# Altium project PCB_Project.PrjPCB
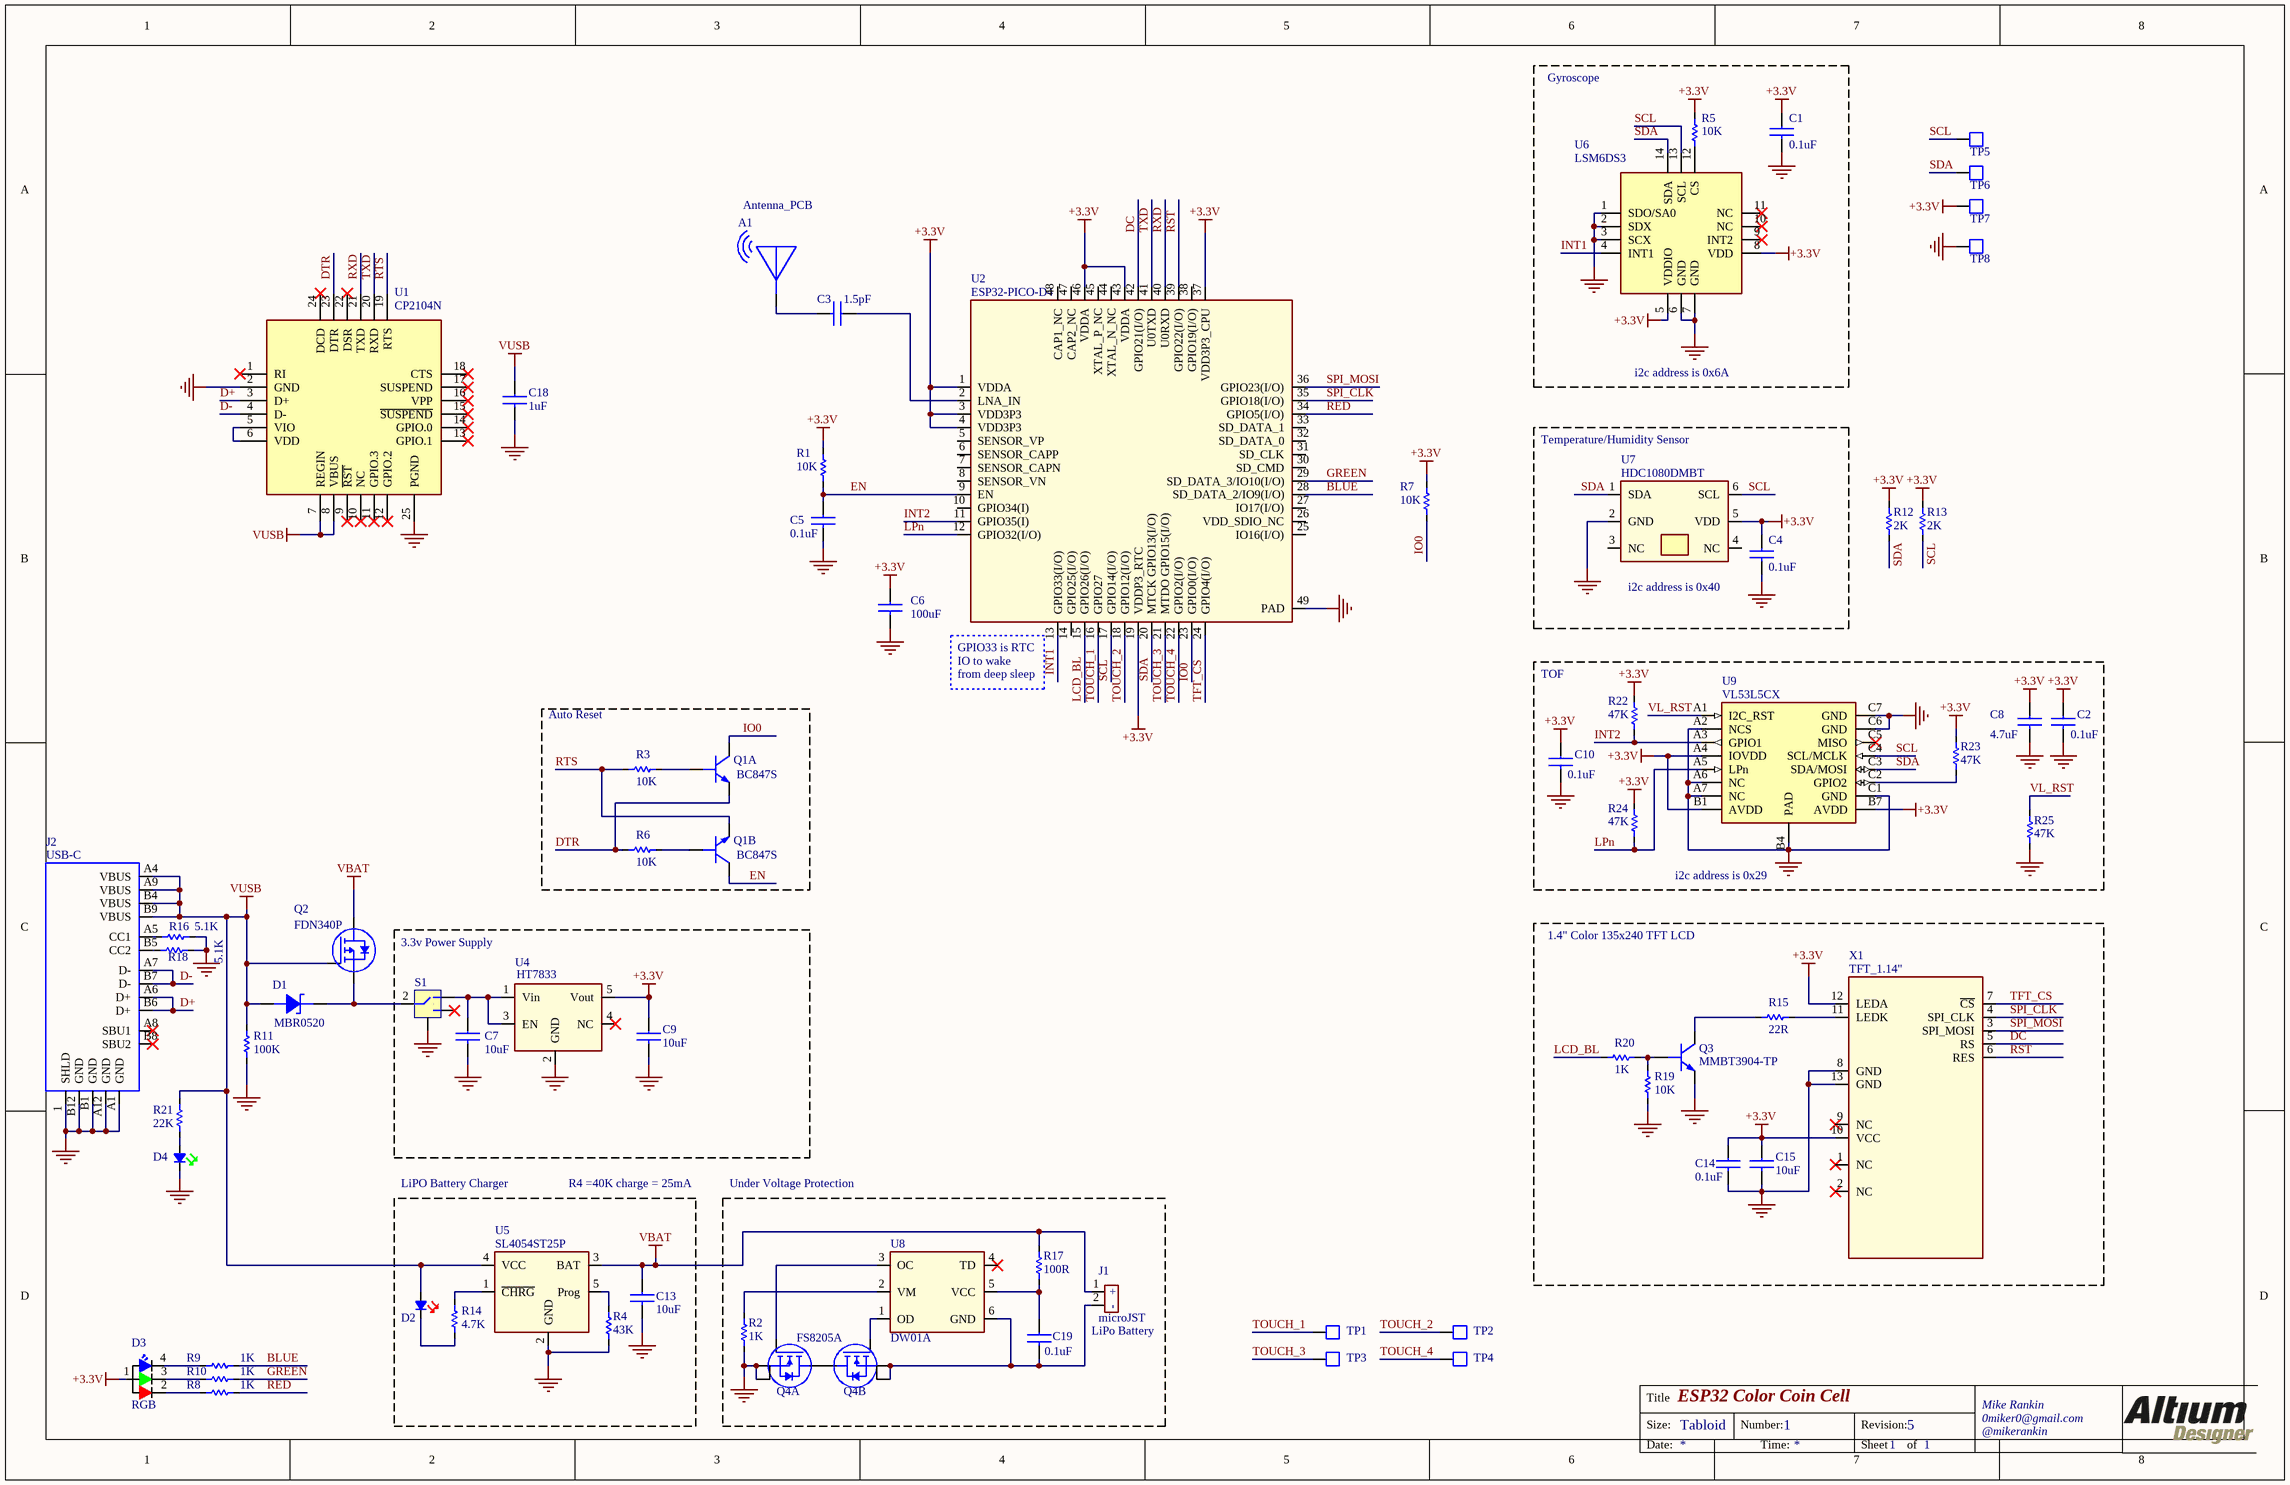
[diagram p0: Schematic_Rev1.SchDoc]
1 sheet, 69 parts. Net scope: global (net labels, ports and power ports of the same name join across sheets).
Board file: PCB_Sensor_Rev1.PcbDoc

## Sheet Schematic_Rev1.SchDoc: ESP32 Color Coin Cell
size Tabloid; DrawnBy: x; Engineer: x; Address1: Mike Rankin; Address2: 0miker0@gmail.com; Address3: @mikerankin; DocumentNumber: 1; Revision: 5; SheetNumber: 1; SheetTotal: 1

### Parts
A1  Antenna_PCB  [ANTENNA PCB]
C1  0.1uF  [CAPC1005X56N]
C2  0.1uF  [CAPC1005X56N]
C3  1.5pF  [CAPC1005X56N]
C4  0.1uF  [CAPC1005X56N]
C5  0.1uF  [CAPC1005X56N]
C6  100uF  [CAPC3216X160L]
C7  10uF  [CAPC2012X140N]
C8  4.7uF  [CAPC2012X140N]
C9  10uF  [CAPC2012X140N]
C10  0.1uF  [CAPC1005X56N]
C13  10uF  [CAPC2012X140N]
C14  0.1uF  [CAPC1005X56N]
C15  10uF  [CAPC2012X140N]
C18  1uF  [CAPC1005X56N]
C19  0.1uF  [CAPC1005X56N]
D1  MBR0520  [SOD123]
D2  Red Led  [LED1005X40N-Red]  (value not drawn)
D3  RGB  [FC-B1010RGBT-HG]
D4  Green Led  [LED1005X40N-Green]  (value not drawn)
J1  CON2  [JST_Micro_2PIN]  (value not drawn)  (no BOM)
J2  USB-C  [TYPE-C-31-M-12]
Q1  BC847S  [SOT65P210X110-6N]  (parts A,B of 2)
Q2  FDN340P  [SOT95P240X110-3N]
Q3  MMBT3904-TP  [SOT95P240X110-3N]
Q4  FS8205A  [TSOP65P490X110-8N WIDE]  (value not drawn)  (parts A,B of 2)
R1  10K  [RESC1005X40L]
R2  1K  [RESC1005X40L]
R3  10K  [RESC1005X40L]
R4  43K  [RESC1005X40L]
R5  10K  [RESC1005X40L]
R6  10K  [RESC1005X40L]
R7  10K  [RESC1005X40L]
R8  1K  [RESC1005X40L]
R9  1K  [RESC1005X40L]
R10  1K  [RESC1005X40L]
R11  100K  [RESC1005X40L]
R12  2K  [RESC1005X40L]
R13  2K  [RESC1005X40L]
R14  4.7K  [RESC1005X40L]
R15  22R  [RESC1005X40L]
R16  5.1K  [RESC1005X40L]
R17  100R  [RESC1005X40L]
R18  5.1K  [RESC1005X40L]
R19  10K  [RESC1005X40L]
R20  1K  [RESC1005X40L]
R21  22K  [RESC1005X40L]
R22  47K  [RESC1005X40L (0402 FOOTPRINT)]
R23  47K  [RESC1005X40L (0402 FOOTPRINT)]
R24  47K  [RESC1005X40L (0402 FOOTPRINT)]
R25  47K  [RESC1005X40L (0402 FOOTPRINT)]
S1  SWITCH SLIDE  [K3-1296S-E1]  (value not drawn)
TP1  Test Point, 1mm Top Layer  [TP100TL]  (value not drawn)  (no BOM)
TP2  Test Point, 1mm Top Layer  [TP100TL]  (value not drawn)  (no BOM)
TP3  Test Point, 1mm Top Layer  [TP100TL]  (value not drawn)  (no BOM)
TP4  Test Point, 1mm Top Layer  [TP100TL]  (value not drawn)  (no BOM)
TP5  Test Point, 1mm Top Layer  [TP100TL]  (value not drawn)  (no BOM)
TP6  Test Point, 1mm Top Layer  [TP100TL]  (value not drawn)  (no BOM)
TP7  Test Point, 1mm Top Layer  [TP100TL]  (value not drawn)  (no BOM)
TP8  Test Point, 1mm Top Layer  [TP100TL]  (value not drawn)  (no BOM)
U1  CP2104N  [24-QFN]
U2  ESP32-PICO-D4  [QFN48_NEWEST]
U4  HT7833  [SOT95P280X144-5N]
U5  SL4054ST25P  [SOT95P280X144-5N]
U6  LSM6DS3  [LSM6DS3]
U7  HDC1080DMBT  [HDC1080]
U8  DW01A  [SOT95P280X130-6N]
U9  value VL53L5CX  [VL53L5CPV0GC/1]  (hidden comment: TOF Sensor)
X1  TFT_1.14"  [TFT_GLASS 1.14 INCH]

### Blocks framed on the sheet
Auto Reset: Q1 R3 R6
3.3v Power Supply: C7 C9 S1 U4
1.4" Color 135x240 TFT LCD: C14 C15 Q3 R15 R19 R20 X1

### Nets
+3.3V: C1.1 C2.1 C4.1 C6.1 C8.1 C9.1 C10.1 C14.1 C15.1 D3.1 R1.1 R5.1 R7.1 R12.2 R13.2 R22.2 R23.2 R24.2 TP7.1 U2.1(VDDA) U2.3(VDD3P3) U2.4(VDD3P3) U2.19(VDDP3_RTC) U2.37(VDD3P3_CPU) U2.43(VDDA) U2.46(VDDA) U4.5(Vout) U6.5(VDDIO) U6.8(VDD) U7.5(VDD) U9.A4(IOVDD) U9.B1(AVDD) U9.B7(AVDD) X1.10(VCC) X1.12(LEDA)
GND: C1.2 C2.2 C4.2 C5.2 C6.2 C7.2 C8.2 C9.2 C10.2 C13.2 C14.2 C15.2 C18.2 D4.1 J2.1(SHLD) J2.A1(GND) J2.A12(GND) J2.B1(GND) J2.B12(GND) Q3.2(E) Q4.2(S) Q4.3(S) R2.1 R4.2 R11.2 R16.2 R18.2 R19.2 R25.1 S1.4 TP8.1 U1.2(GND) U1.25(PGND) U2.49(PAD) U4.2(GND) U5.2(GND) U6.1(SDO/SA0) U6.2(SDX) U6.3(SCX) U6.6(GND) U6.7(GND) U7.2(GND) U9.A2(NCS) U9.A6(NC) U9.A7(NC) U9.B4(PAD) U9.C1(GND) U9.C6(GND) U9.C7(GND) X1.8(GND) X1.13(GND)
VBAT: C13.1 J1.1 Q2.3(D) R17.2 U5.3(BAT)
VUSB: C18.1 D1.2(Annode) D2.2 J2.A4(VBUS) J2.A9(VBUS) J2.B4(VBUS) J2.B9(VBUS) Q2.1(G) R11.1 R21.2 U1.7(REGIN) U1.8(VBUS) U5.4(VCC)
BLUE: R9.2 U2.28(SD_DATA_2/IO9(I/O))
D+: J2.A6(D+) J2.B6(D+) U1.3(D+)
D-: J2.A7(D-) J2.B7(D-) U1.4(D-)
DC: U2.42(GPIO21(I/O)) X1.5(RS)
DTR: Q1.1(E1) R6.2 U1.23(DTR)
EN: C5.1 Q1.3(C2) R1.2 U2.9(EN)
GREEN: R10.2 U2.29(SD_DATA_3/IO10(I/O))
INT1: U2.13(GPIO33(I/O)) U6.4(INT1)
INT2: R22.1 U2.11(GPIO35(I)) U9.A3(GPIO1)
IO0: Q1.6(C1) R7.2 U2.23(GPIO0(I/O))
LCD_BL: R20.1 U2.15(GPIO26(I/O))
LPn: R24.1 U2.12(GPIO32(I/O)) U9.A5(LPn)
RED: R8.2 U2.34(GPIO5(I/O))
RST: U2.39(GPIO22(I/O)) X1.6(RES)
RTS: Q1.4(E2) R3.2 U1.19(RTS)
RXD: U1.21(TXD) U2.40(U0RXD)
SCL: R13.1 TP5.1 U2.17(GPIO14(I/O)) U6.13(SCL) U7.6(SCL) U9.C4(SCL/MCLK)
SDA: R12.1 TP6.1 U2.20(MTCK_GPIO13(I/O)) U6.14(SDA) U7.1(SDA) U9.C3(SDA/MOSI)
SPI_CLK: U2.35(GPIO18(I/O)) X1.4(SPI_CLK)
SPI_MOSI: U2.36(GPIO23(I/O)) X1.3(SPI_MOSI)
TFT_CS: U2.24(GPIO4(I/O)) X1.7(~{CS})
TOUCH_1: TP1.1 U2.16(GPIO27)
TOUCH_2: TP2.1 U2.18(GPIO12(I/O))
TOUCH_3: TP3.1 U2.21(MTDO_GPIO15(I/O))
TOUCH_4: TP4.1 U2.22(GPIO2(I/O))
TXD: U1.20(RXD) U2.41(U0TXD)
VL_RST: R25.2 U9.A1(I2C_RST)
NetA1_1: A1.1 C3.2
NetC3_1: C3.1 U2.2(LNA_IN)
NetC7_1: C7.1 S1.1 U4.1(Vin) U4.3(EN)
NetC19_1: C19.1 R17.1 U8.5(VCC)
NetC19_2: C19.2 J1.2 Q4.6(S) Q4.7(S) U8.6(GND)
NetD1_1: D1.1(Cathode) Q2.2(S) S1.2
NetD2_1: D2.1 R14.1
NetD3_2: D3.2 R8.1
NetD3_3: D3.3 R10.1
NetD3_4: D3.4 R9.1
NetD4_2: D4.2 R21.1
NetJ2_A5: J2.A5(CC1) R16.1
NetJ2_B5: J2.B5(CC2) R18.1
NetQ1_2: Q1.2(B1) R3.1
NetQ1_5: Q1.5(B2) R6.1
NetQ3_1: Q3.1(B) R19.1 R20.2
NetQ3_3: Q3.3(C) R15.2
NetQ4_1: Q4.1(D) Q4.8(D)
NetQ4_4: Q4.4(G) U8.3(OC)
NetQ4_5: Q4.5(G) U8.1(OD)
NetR2_2: R2.2 U8.2(VM)
NetR4_1: R4.1 U5.5(Prog)
NetR5_2: R5.2 U6.12(CS)
NetR14_2: R14.2 U5.1(~{CHRG})
NetR15_1: R15.1 X1.11(LEDK)
NetR23_1: R23.1 U9.C2(GPIO2)
NetU1_5: U1.5(VIO) U1.6(VDD)

Not connected (* = marked no-connect by the designer): J2 A8(SBU1)* B8(SBU2)*; S1 3*; U1 1(RI)* 9(~{RST})* 10(NC)* 11(GPIO.3)* 12(GPIO.2)* 13(GPIO.1)* 14(GPIO.0)* 15(~{SUSPEND})* 16(VPP)* 17(SUSPEND)* 18(CTS)* 22(DSR)* 24(DCD)*; U2 5(SENSOR_VP) 6(SENSOR_CAPP) 7(SENSOR_CAPN) 8(SENSOR_VN) 10(GPIO34(I)) 14(GPIO25(I/O)) 25(IO16(I/O)) 26(VDD_SDIO_NC) 27(IO17(I/O)) 30(SD_CMD) 31(SD_CLK) 32(SD_DATA_0) 33(SD_DATA_1) 38(GPIO19(I/O)) 44(XTAL_N_NC) 45(XTAL_P_NC) 47(CAP2_NC) 48(CAP1_NC); U4 4(NC)*; U6 9(INT2)* 10(NC)* 11(NC)*; U7 3(NC) 4(NC); U8 4(TD)*; U9 C5(MISO)*; X1 1(NC)* 2(NC)* 9(NC)*

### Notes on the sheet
- Gyroscope
- i2c address is 0x6A
- (near U7) Temperature/Humidity Sensor
- i2c address is 0x40
- (near U2) GPIO33 is RTC
- (near U2) IO to wake
- (near U2) from deep sleep
- TOF
- i2c address is 0x29
- LiPO Battery Charger
- R4 =40K charge = 25mA
- Under Voltage Protection
- (near J1) LiPo Battery
- (near J1) microJST
- Labels drawn without touching a wire or pin: ~{}

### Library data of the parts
A1 = Antenna_PCB: Antenna PCB 2.4G; Value: PCB Antenna
C1 C2 C4 C5 C10 C14 C19 = CAP_0402: CAP 0.1uF 0402; PartNumber: C344190; Manufacturer: CCTC; Vendor: LCSC
C3 = CAP_0402: CAP 1.5pF 0402; Part_Number: C147344; Manufacturer: Dafron; Part_Footprint: 0402; Vendor: LCSC
C6 = CAP_1206: CAP 100uF 6.3V 1206; PartNumber: C87164; Manufacturer: Taiyo Yuden; Vendor: LCSC
C7 C9 C15 = CAP_0805: CAP 10uF 0805; Manufacturer: Samsung; PartNumber: C307520; Vendor: LCSC
C8 = CAP_0805: CAP 4.7uF 0805
C13 = CAP_0805: CAP 10uF 0805; PartNumber: C307520; Manufacturer: Samsung; Vendor: LCSC
C18 = CAP_0603: CAP 1uF 16V 0402; PartNumber: C83063; Manufacturer: Walsin; Vendor: LCSC
D1 = MBR0520-TP: DIODE SCHOTTKY 20V 500MA SOD123; Manufacturer: CJ; PartNumber: C475717; Vendor: LCSC
D2 = LED_0402_SMALL_Red: LED RED 0603; Part_Number: C364556; Part_Footprint: 0402; Vendor: LCSC
D3 = FC-B1010RGBT-HG: LED,RGB LED,SMD,RoHS; PartNumber: C158099; Manufacturer: Foshan; Vendor: LCSC; Value: RGB Led
D4 = LED_0402_SMALL_GREEN: LED Green 0402; Part_Number: C74338; Part_Footprint: 0402; Vendor: LCSC
J1 = JST_Micro_CONN_2PIN: JST MIcro CONN 2POS
J2 = USB-C: CONN RECPT USB-C; Manufacturer: KHE; Part_Number: C165948; Part_Footprint: SMT; Vendor: LCSC
Q1 = BC847S: TRANS 2NPN 44V 0.1A SC-70-6; Manufacturer: Changjiang; Vendor: LCSC
Q2 = FDN340P: MOSFET P-CH 20V 2A SOT-23; Manufacturer: On Semi; Part_Number: C75469; Vendor: LCSC
Q3 = MMBT3904-TP: TRANSISTOR NPN SOT23; Manufacturer: Micro Commercial; PartNumber: C668969; Vendor: LCSC
Q4 = FS8205A: MOSFET 2N-CH 20V 6A TSSOP-8L; Manufacturer: Fortune; PartNumber: C16052; Vendor: LCSC
R1 R3 R5-R7 R19 = RES_0402: RES 10K 0402; PartNumber: C258091; Manufacturer: Guangdong; Vendor: LCSC
R2 R8-R10 R20 = RES_0402: RES 1K 0402; PartNumber: C106235; Manufacturer: Yageo; Vendor: LCSC
R4 = RES_0603: RES 43K 0402; Manufacturer: Uniroyal; PartNumber: C8329; Vendor: LCSC
R11 = RES_0603: RES 100K 0402; Manufacturer: Uniroyal Elec; PartNumber: C25741; Vendor: LCSC
R12 R13 = RES_0402: RES 2K 0402; Manufacturer: LIZ Elec; PartNumber: C100291; Vendor: LCSC
R14 = RES_0603: RES 4.7K 0402; Manufacturer: LIZ Elec; PartNumber: C100139; Vendor: LCSC
R15 = RES_0402: RES 22R 0402; PartNumber: C25092; Manufacturer: Uniroyal; Vendor: LCSC
R16 R18 = RES_0603: RES 5.1K 0402; Vendor: LCSC
R17 = RES_0603: RES 100R 0402; Manufacturer: Yageo; PartNumber: C106232; Vendor: LCSC
R21 = RES_0603: RES 22K 0402; Manufacturer: LIZ Elec; PartNumber: C100310; Vendor: LCSC
R22-R25 = RES_0402: RES 47K 0402; Vendor: LCSC
S1 = K3-1296S-E1: SWITCH SLIDE SMD; Manufacturer: Korean Hroparts Elec; PartNumber: C128955; Vendor: LCSC
U1 = CP2104N: IC BRIDGE USB TO UART 24QFN; Manufacturer: Silicon Labs; PartNumber: C47742; Vendor: LCSC
U2 = ESP32-PICO-D4: RF Transceiver ICs QFN-48_7x7x05P RoHS; Manufacturer: Espressif; PartNumber: C193707; Vendor: LCSC
U4 = HT7833: IC LDO 3.3V 0.5A SOT23-5; Manufacturer: Holtek; PartNumber: C164106; Vendor: LCSC
U5 = SL4054ST25P: Charger IC Lithium-Ion/Polymer SOT23-5; Manufacturer: Techfuse; PartNumber: C258510; Vendor: LCSC
U6 = LSM6DS3 (obsolete): IMU ACCEL/GYRO I2C/SPI 14VFLGA; Manufacturer: ST MICRO; Part_Number: LSM6DS3TR; Vendor: LCSC
U7 = HDC1080DMBT: Humidity/Temperature Sensor; Manufacturer: Texas Instruments; PartNumber: C82227; Vendor: LCSC
U8 = DW01A: IC LITHIUM BATT PROTECT SOT-23-6L; Manufacturer: PUOLOP; PartNumber: C351410; Vendor: LCSC
U9 = VL53L5CXV0GC/1: IC,LASER SENSOR,17pin; Manufacturer: ST MICRO
X1 = TFT_GLASS 1.14 INCH COLOR: 1.14 INCH TFT GLASS COLOR; Part_Number: ER-TFT1.14-1; Manufacturer: BuyDisplay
